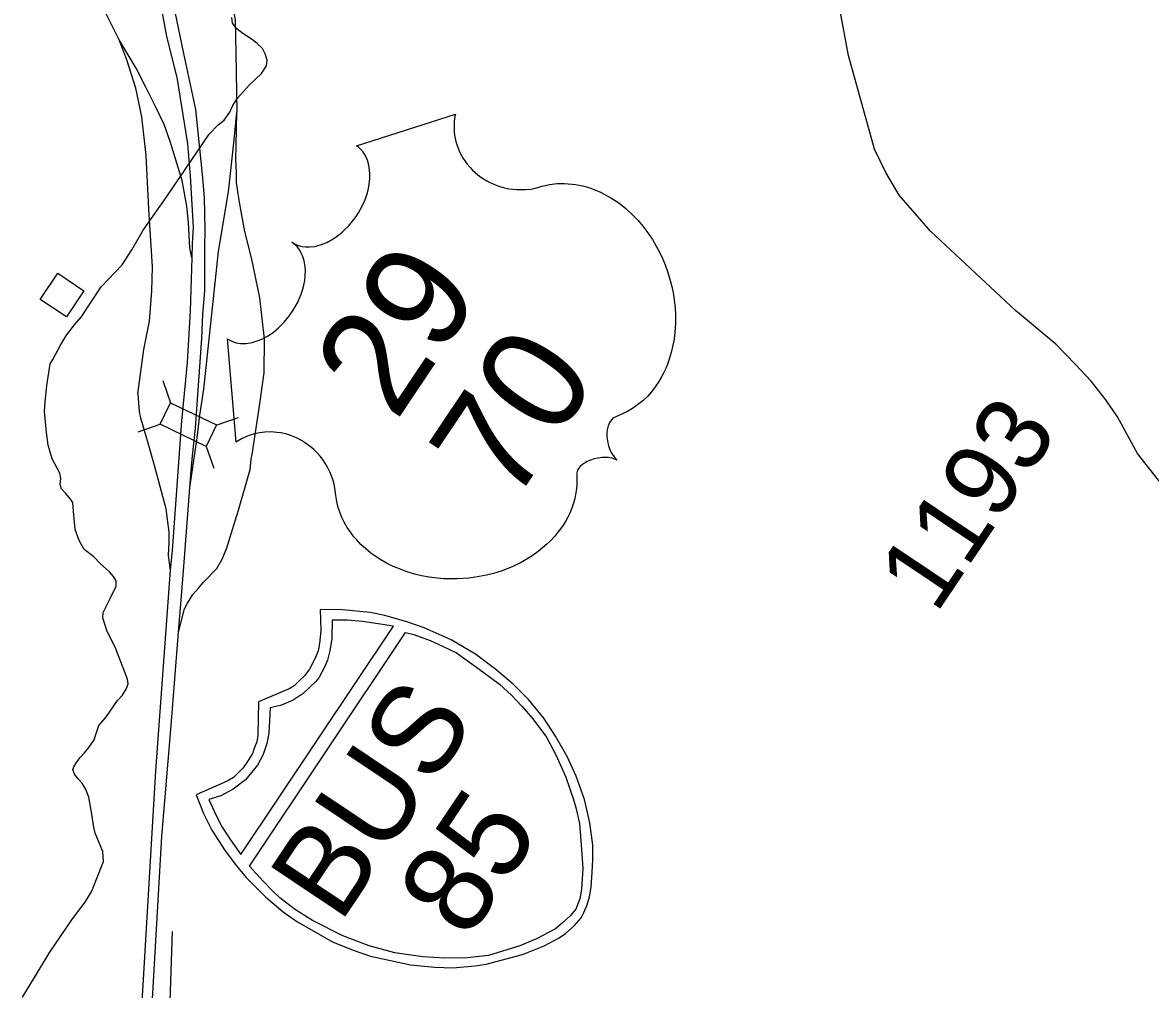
# Model space of a CAD drawing. Extents: x 1716282 to 1717158, y 799307 to 801078.
# Drawn here: x 1716546.8 to 1716655.2, y 800547.7 to 800640.6 of the extents above; entities that cross this region are included whole.
import ezdxf

# ---------------------------------------------------------------- set-up
doc = ezdxf.new("R2010")
doc.units = 0
for name, color, linetype in [('Exist Hydrographic Creek Single Shore', 7, 'Continuous'), ('Exist Road Non-System Structure Non-Sys NCDOT Attributed CELL', 7, 'Continuous'), ('Exist Road Non-System Structure Non-Sys Other Attributed CELL', 7, 'Continuous'), ('Exist Road Primary Interstate Divided Center Attributed', 7, 'Continuous'), ('Exist Road Primary Interstate Ramp 1 Lane Attributed', 7, 'Continuous'), ('Exist Road Secondary Type 51 Attributed', 7, 'Continuous'), ('Old_Level_1', 7, 'Continuous'), ('Old_Level_2', 7, 'Continuous')]:
    doc.layers.add(name, color=color, linetype=linetype)

msp = doc.modelspace()

# ---------------------------------------------------------------- linework, layer by layer
at = {"layer": 'Exist Hydrographic Creek Single Shore'}
for points in [[(1716551.4, 800594.83), (1716550.95, 800595.35), (1716550.56, 800595.81), (1716550.42, 800596.23), (1716550.49, 800596.81), (1716550.38, 800597.32), (1716549.64, 800598.68), (1716549.25, 800600.02), (1716549.1, 800601.22), (1716548.91, 800603.23), (1716548.96, 800604.17), (1716549.13, 800605.71), (1716549.27, 800606.57), (1716549.45, 800607.82), (1716549.71, 800608.25), (1716550.46, 800609.61), (1716551.04, 800610.58), (1716551.78, 800611.58), (1716552.43, 800612.32), (1716554.35, 800615.22), (1716556.37, 800617.34), (1716557.31, 800618.79), (1716558.39, 800620.68), (1716559.54, 800622.3), (1716560.68, 800623.92), (1716564.75, 800629.91), (1716565.6, 800630.8), (1716566.18, 800631.25), (1716566.73, 800632.01), (1716567.02, 800632.67), (1716567.46, 800633.36), (1716568.58, 800634.63), (1716569.76, 800635.74), (1716570.25, 800636.46), (1716570.31, 800637.02), (1716570.12, 800637.63), (1716569.88, 800638.14), (1716569.37, 800638.62), (1716568.92, 800638.97), (1716567.99, 800639.59), (1716567.4, 800640.02), (1716566.97, 800640.58), (1716566.92, 800641.11)], [(1716546.8, 800546.93), (1716547.95, 800548.84), (1716549.37, 800551.16), (1716551.53, 800554.38), (1716552.08, 800555.1), (1716552.83, 800556.06), (1716553.46, 800557.12), (1716553.92, 800558.28), (1716554.58, 800559.97), (1716554.53, 800560.93), (1716553.78, 800562.72), (1716553.61, 800563.44), (1716553.51, 800564.33), (1716553.17, 800566.16), (1716552.89, 800566.89), (1716552.54, 800567.5), (1716552.12, 800567.97), (1716551.78, 800568.37), (1716551.62, 800568.84), (1716551.77, 800569.14), (1716552.06, 800569.61), (1716552.34, 800569.97), (1716552.77, 800570.42), (1716553.18, 800570.95), (1716553.7, 800571.67), (1716553.87, 800572.28), (1716554.15, 800573.07), (1716554.74, 800573.75), (1716555.11, 800574.24), (1716555.92, 800575.45), (1716556.42, 800575.97), (1716556.77, 800576.56), (1716556.97, 800577.06), (1716556.89, 800577.51), (1716555.77, 800580.42), (1716554.91, 800582.18), (1716554.51, 800583.42), (1716554.56, 800583.92), (1716554.86, 800584.56), (1716555.24, 800585.26), (1716555.79, 800586.45), (1716555.8, 800586.96), (1716555.56, 800587.37), (1716555.15, 800587.82), (1716554.28, 800588.6), (1716553.67, 800589.27), (1716552.74, 800589.96), (1716552.23, 800590.85), (1716551.87, 800591.91), (1716551.7, 800593.65), (1716551.65, 800594.48), (1716551.4, 800594.83)]]:
    msp.add_lwpolyline(points, dxfattribs=at)
at = {"layer": 'Exist Road Non-System Structure Non-Sys NCDOT Attributed CELL'}
for p, q in [((1716560.3, 800606.21), (1716561.03, 800604.09)), ((1716557.91, 800601.3), (1716560.03, 800602.03)), ((1716565.43, 800601.94), (1716567.55, 800602.67)), ((1716564.44, 800599.89), (1716565.19, 800597.81))]:
    msp.add_line(p, q, dxfattribs=at)
msp.add_lwpolyline([(1716561.03, 800604.09), (1716565.44, 800601.95), (1716564.44, 800599.89), (1716560.03, 800602.03)], close=True, dxfattribs=at)
at = {"layer": 'Exist Road Non-System Structure Non-Sys Other Attributed CELL'}
msp.add_lwpolyline([(1716548.51, 800614.02), (1716550.19, 800616.53), (1716552.7, 800614.85), (1716551.02, 800612.34)], close=True, dxfattribs=at)
at = {"layer": 'Exist Road Primary Interstate Divided Center Attributed'}
for points in [[(1716558.5, 800649.75), (1716559.41, 800645.93), (1716560.64, 800639.31), (1716561.62, 800635.36), (1716562.66, 800628.98), (1716562.93, 800625.9), (1716563.2, 800620.92), (1716563.12, 800619.44), (1716563.06, 800618.01)], [(1716563.42, 800601.65), (1716564.03, 800610.28), (1716564.13, 800612.56), (1716564.31, 800614.83), (1716564.34, 800616.94), (1716564.33, 800619.08), (1716564.37, 800620.73), (1716564.28, 800623.82), (1716564.1, 800626.04), (1716563.45, 800632.27), (1716562.3, 800637.66), (1716560.63, 800645.71), (1716559.74, 800649.78)], [(1716563.06, 800618.01), (1716562.9, 800612.89), (1716562.62, 800607.99), (1716562.48, 800606.3), (1716562.07, 800602.34)], [(1716562.07, 800602.34), (1716561.17, 800589.87), (1716560.99, 800587.98)], [(1716562.88, 800595.9), (1716563.01, 800597.56), (1716563.13, 800598.98), (1716563.42, 800601.65)], [(1716561.78, 800582.04), (1716562.05, 800585.14), (1716562.26, 800587.93), (1716562.88, 800595.9)], [(1716560.99, 800587.98), (1716559.59, 800568.69), (1716558.25, 800545.95), (1716557.97, 800539.29), (1716557.81, 800532.9)], [(1716558.45, 800531), (1716558.55, 800536.61), (1716559.23, 800545.66), (1716560.2, 800562.39), (1716561.08, 800573.07), (1716561.78, 800582.04)]]:
    msp.add_lwpolyline(points, dxfattribs=at)
at = {"layer": 'Exist Road Primary Interstate Ramp 1 Lane Attributed'}
for points in [[(1716556.09, 800638.97), (1716554.22, 800642.7), (1716553.9, 800643.44), (1716553.38, 800644.7), (1716552.96, 800646.13), (1716552.59, 800647.62), (1716552.15, 800649.72)], [(1716565.79, 800649.91), (1716567.23, 800640.82), (1716567.3, 800637.71), (1716567.39, 800632.02)], [(1716557.88, 800604.95), (1716558.45, 800609.2), (1716559.01, 800611.93), (1716559.24, 800614.84), (1716559.31, 800617.16), (1716558.95, 800622.69), (1716558.69, 800627.87), (1716558.27, 800631.56), (1716557.69, 800634.34), (1716556.84, 800637.05), (1716556.09, 800638.97)], [(1716563.06, 800618.01), (1716562.88, 800618.98), (1716562.75, 800621.41), (1716562.61, 800622.99), (1716562.14, 800625.45), (1716561, 800629.21), (1716560.41, 800630.83), (1716559.6, 800632.5), (1716558.64, 800634.41), (1716557.73, 800636.24), (1716556.09, 800638.97)], [(1716562.88, 800595.9), (1716563.6, 800600.7), (1716563.86, 800602.89), (1716564.22, 800605.38), (1716565.63, 800618.62), (1716566.59, 800624.36), (1716567.13, 800629.35), (1716567.39, 800632.02)], [(1716568.87, 800599.11), (1716569.51, 800603.34), (1716570.03, 800606.97), (1716570.06, 800610.21), (1716569.61, 800614.18), (1716568.83, 800617.89), (1716568.16, 800620.56), (1716567.76, 800622.82), (1716567.53, 800624.18), (1716567.38, 800625.25), (1716567.38, 800626.26), (1716567.29, 800627.5), (1716567.34, 800628.78), (1716567.39, 800632.02)], [(1716557.88, 800604.95), (1716557.97, 800603.62), (1716558.05, 800603.01), (1716558.15, 800602.63), (1716558.26, 800602.23), (1716558.86, 800600.22), (1716559.47, 800598.09), (1716560.03, 800595.94), (1716560.56, 800593.92), (1716560.7, 800592.85), (1716560.85, 800591.63), (1716560.87, 800590.7), (1716560.81, 800589.4), (1716560.99, 800587.98)], [(1716561.78, 800582.04), (1716562.38, 800584.26), (1716562.65, 800584.83), (1716563.16, 800585.66), (1716563.72, 800586.27), (1716564.21, 800586.85), (1716565.47, 800588.16), (1716565.95, 800588.97), (1716566.41, 800590.05), (1716566.71, 800590.98), (1716567.55, 800593.76), (1716568.67, 800597.68), (1716568.79, 800598.67), (1716568.87, 800599.11)]]:
    msp.add_lwpolyline(points, dxfattribs=at)
at = {"layer": 'Exist Road Secondary Type 51 Attributed'}
for points in [[(1716695.67, 800558.39), (1716688.08, 800565.49), (1716681.92, 800571.19), (1716675.73, 800576.67), (1716668.88, 800582.96), (1716664.29, 800587.01), (1716662.56, 800588.64), (1716660.27, 800591.22), (1716653.98, 800599.21), (1716652.07, 800602.74), (1716650.94, 800604.38), (1716649.53, 800606.17), (1716648.03, 800607.76), (1716646.14, 800609.72), (1716642.26, 800612.96), (1716634.1, 800620.58), (1716631.07, 800624.03), (1716629.78, 800626.22), (1716628.69, 800628.46), (1716626.21, 800637.47), (1716625.41, 800641.76), (1716625.31, 800647.59), (1716627.05, 800656.51), (1716628.42, 800665.05)], [(1716560.43, 800531.91), (1716560.4, 800533.68), (1716560.71, 800540.38), (1716560.99, 800546.56), (1716561.23, 800553.26)]]:
    msp.add_lwpolyline(points, dxfattribs=at)
at = {"layer": 'Old_Level_2'}
for points in [[(1716566.5, 800610.22), (1716566.78, 800610.06), (1716567.14, 800609.91), (1716567.34, 800609.85), (1716567.76, 800609.79), (1716568.29, 800609.79), (1716568.88, 800609.88), (1716569.46, 800610.06), (1716569.8, 800610.21), (1716570.34, 800610.49), (1716570.88, 800610.85), (1716571.42, 800611.3), (1716571.92, 800611.79), (1716572.4, 800612.37), (1716572.83, 800612.98), (1716573.22, 800613.68), (1716573.57, 800614.51), (1716573.71, 800614.91), (1716573.84, 800615.38), (1716573.93, 800615.83), (1716573.98, 800616.35), (1716573.99, 800616.8), (1716573.97, 800617.16), (1716573.88, 800617.72), (1716573.72, 800618.22), (1716573.6, 800618.47), (1716573.49, 800618.69), (1716573.19, 800619.09), (1716573.04, 800619.24), (1716572.7, 800619.51), (1716573.01, 800619.33), (1716573.22, 800619.23), (1716573.44, 800619.16), (1716573.69, 800619.11), (1716574.05, 800619.06), (1716574.39, 800619.06), (1716574.92, 800619.12), (1716575.21, 800619.19), (1716575.46, 800619.26), (1716576.05, 800619.5), (1716576.66, 800619.84), (1716576.94, 800620.02), (1716577.2, 800620.22), (1716577.52, 800620.48), (1716577.83, 800620.77), (1716578.12, 800621.07), (1716578.4, 800621.38), (1716578.66, 800621.71), (1716578.86, 800621.99), (1716579.09, 800622.35), (1716579.29, 800622.69), (1716579.47, 800623.04), (1716579.66, 800623.45), (1716579.79, 800623.79), (1716579.95, 800624.25), (1716580.06, 800624.69), (1716580.13, 800625.09), (1716580.19, 800625.63), (1716580.2, 800626.09), (1716580.17, 800626.46), (1716580.1, 800626.92), (1716579.97, 800627.39), (1716579.85, 800627.7), (1716579.69, 800627.97), (1716579.51, 800628.24), (1716579.3, 800628.47), (1716579.09, 800628.65), (1716578.9, 800628.79), (1716588.41, 800631.82), (1716588.36, 800631.62), (1716588.3, 800631.16), (1716588.28, 800630.77), (1716588.29, 800630.11), (1716588.34, 800629.8), (1716588.39, 800629.49), (1716588.46, 800629.19), (1716588.54, 800628.91), (1716588.67, 800628.55), (1716588.82, 800628.21), (1716589, 800627.85), (1716589.17, 800627.56), (1716589.55, 800627.02), (1716589.82, 800626.7), (1716590.06, 800626.45), (1716590.58, 800625.99), (1716590.85, 800625.78), (1716591.12, 800625.6), (1716591.42, 800625.42), (1716591.71, 800625.27), (1716592.03, 800625.12), (1716592.32, 800625), (1716592.68, 800624.87), (1716593.12, 800624.75), (1716593.56, 800624.66), (1716594.32, 800624.57), (1716595.15, 800624.57), (1716595.65, 800624.63), (1716596.11, 800624.71), (1716596.72, 800624.89), (1716597.05, 800624.97), (1716597.47, 800625.06), (1716598.21, 800625.15), (1716598.54, 800625.16), (1716598.9, 800625.16), (1716599.26, 800625.14), (1716599.64, 800625.11), (1716599.96, 800625.07), (1716600.67, 800624.93), (1716601.32, 800624.73), (1716601.66, 800624.62), (1716602.37, 800624.32), (1716602.72, 800624.15), (1716603.37, 800623.79), (1716604.13, 800623.29), (1716604.8, 800622.75), (1716605.54, 800622.06), (1716605.97, 800621.62), (1716606.43, 800621.06), (1716606.82, 800620.56), (1716607.36, 800619.77), (1716607.72, 800619.15), (1716608.12, 800618.38), (1716608.35, 800617.9), (1716608.57, 800617.35), (1716608.81, 800616.7), (1716609.04, 800615.97), (1716609.25, 800615.14), (1716609.37, 800614.49), (1716609.49, 800613.68), (1716609.54, 800613.21), (1716609.57, 800612.55), (1716609.57, 800611.69), (1716609.52, 800610.87), (1716609.44, 800610.2), (1716609.33, 800609.62), (1716609.17, 800608.9), (1716608.79, 800607.77), (1716608.63, 800607.37), (1716608.41, 800606.92), (1716608.19, 800606.51), (1716607.97, 800606.12), (1716607.63, 800605.61), (1716607.25, 800605.13), (1716606.87, 800604.7), (1716606.43, 800604.28), (1716605.93, 800603.87), (1716605.44, 800603.52), (1716604.88, 800603.2), (1716603.84, 800602.74), (1716603.56, 800602.59), (1716603.44, 800602.48), (1716603.22, 800602.18), (1716603.09, 800601.85), (1716603, 800601.47), (1716602.98, 800601.23), (1716602.98, 800600.88), (1716603, 800600.6), (1716603.06, 800600.24), (1716603.14, 800599.97), (1716603.19, 800599.76), (1716603.4, 800599.29), (1716603.51, 800599.1), (1716603.68, 800598.87), (1716603.95, 800598.58), (1716603.47, 800598.75), (1716603.13, 800598.81), (1716602.8, 800598.83), (1716602.51, 800598.82), (1716602.09, 800598.77), (1716601.76, 800598.7), (1716601.4, 800598.58), (1716601.07, 800598.43), (1716600.82, 800598.29), (1716600.62, 800598.15), (1716600.41, 800597.95), (1716600.26, 800597.77), (1716600.16, 800597.61), (1716600.07, 800597.36), (1716600.08, 800596.93), (1716600.09, 800596.52), (1716600.07, 800596.1), (1716600.02, 800595.61), (1716599.97, 800595.26), (1716599.88, 800594.87), (1716599.76, 800594.42), (1716599.59, 800593.95), (1716599.4, 800593.48), (1716599.22, 800593.09), (1716598.99, 800592.68), (1716598.77, 800592.32), (1716598.52, 800591.96), (1716598.27, 800591.64), (1716597.97, 800591.27), (1716597.57, 800590.82), (1716597.21, 800590.48), (1716596.8, 800590.13), (1716596.37, 800589.78), (1716595.88, 800589.43), (1716595.23, 800589.01), (1716594.74, 800588.74), (1716593.94, 800588.34), (1716592.9, 800587.94), (1716592.06, 800587.68), (1716591.4, 800587.51), (1716590.36, 800587.31), (1716589.7, 800587.23), (1716588.59, 800587.15), (1716587.81, 800587.14), (1716587.26, 800587.17), (1716586.4, 800587.24), (1716585.88, 800587.32), (1716585.14, 800587.46), (1716584.49, 800587.62), (1716583.88, 800587.79), (1716583.51, 800587.92), (1716582.87, 800588.17), (1716582.43, 800588.35), (1716581.84, 800588.64), (1716581.24, 800588.99), (1716580.71, 800589.33), (1716580.28, 800589.63), (1716579.81, 800590.03), (1716579.32, 800590.47), (1716578.93, 800590.89), (1716578.66, 800591.2), (1716578.35, 800591.61), (1716578.02, 800592.1), (1716577.73, 800592.6), (1716577.51, 800593.04), (1716577.3, 800593.55), (1716577.15, 800594.02), (1716577.01, 800594.6), (1716576.91, 800595.16), (1716576.86, 800595.65), (1716576.75, 800596.27), (1716576.66, 800596.61), (1716576.5, 800597.06), (1716576.34, 800597.44), (1716576.18, 800597.76), (1716575.94, 800598.21), (1716575.73, 800598.52), (1716575.4, 800598.96), (1716575.14, 800599.24), (1716574.8, 800599.58), (1716574.46, 800599.88), (1716574.01, 800600.21), (1716573.62, 800600.45), (1716573.14, 800600.7), (1716572.65, 800600.91), (1716572.21, 800601.06), (1716571.67, 800601.18), (1716571.26, 800601.24), (1716570.67, 800601.28), (1716570.09, 800601.27), (1716569.57, 800601.2), (1716569.09, 800601.1), (1716568.69, 800600.97), (1716568.33, 800600.84), (1716567.91, 800600.64), (1716567.54, 800600.43), (1716567.33, 800600.28)], [(1716600.49, 800554.55), (1716600.76, 800555.07), (1716601.07, 800555.8), (1716601.29, 800556.57), (1716601.45, 800557.5), (1716601.57, 800558.95), (1716601.64, 800560.13), (1716601.64, 800561.56), (1716601.32, 800563.69), (1716600.82, 800565.95), (1716600.02, 800568.18), (1716599.17, 800570.09), (1716598.03, 800572.04), (1716596.91, 800573.77), (1716595.48, 800575.52), (1716593.98, 800577.04), (1716592.29, 800578.43), (1716590.36, 800579.9), (1716588, 800581.28), (1716585.42, 800582.44), (1716583.73, 800583.03), (1716581.63, 800583.63), (1716580.22, 800583.91), (1716577.56, 800584.16), (1716575.42, 800584.21), (1716575.47, 800582.17), (1716575.34, 800580.95), (1716575.22, 800580.23), (1716574.95, 800579.59), (1716574.38, 800578.46), (1716573.91, 800577.83), (1716573.37, 800577.31), (1716572.91, 800576.87), (1716572.43, 800576.59), (1716569.47, 800575.32), (1716569.41, 800572.09), (1716569.31, 800571.48), (1716569.09, 800570.93), (1716568.91, 800570.37), (1716568.43, 800569.58), (1716568.02, 800569), (1716567.51, 800568.47), (1716567.09, 800568.06), (1716566.47, 800567.7), (1716563.48, 800566.38), (1716564.19, 800564.6), (1716564.99, 800563), (1716566.29, 800561), (1716567.38, 800559.57), (1716568.31, 800558.45), (1716570.16, 800556.59), (1716571.87, 800555.13), (1716573.16, 800554.21), (1716576.6, 800552.26), (1716578.59, 800551.45), (1716580.25, 800550.87), (1716584.11, 800550.04), (1716586.43, 800549.81), (1716588.18, 800549.77), (1716590.3, 800549.94), (1716591.36, 800550.1), (1716594.87, 800551.04), (1716596.93, 800551.87), (1716598.4, 800552.64), (1716599, 800553.07), (1716599.84, 800553.79)], [(1716564.72, 800565.95), (1716565.21, 800564.81), (1716565.94, 800563.39), (1716566.8, 800562.07), (1716567.77, 800560.65), (1716582.46, 800582.59), (1716580.98, 800582.84), (1716579.47, 800583.06), (1716578.04, 800583.19), (1716576.57, 800583.17), (1716576.52, 800581.42), (1716576.34, 800580.24), (1716576.11, 800579.35), (1716575.84, 800578.65), (1716575.28, 800577.65), (1716574.97, 800577.25), (1716573.79, 800576.13), (1716572.83, 800575.48), (1716571.69, 800575.01), (1716570.59, 800574.76), (1716570.47, 800572.32), (1716570.3, 800571.32), (1716569.93, 800570.28), (1716569.4, 800569.23), (1716568.24, 800567.84), (1716567.05, 800566.94), (1716565.85, 800566.28)], [(1716583.63, 800581.99), (1716584.41, 800581.81), (1716586, 800581.22), (1716587.18, 800580.68), (1716588.51, 800580.03), (1716590.56, 800578.57), (1716592.66, 800577.02), (1716593.81, 800575.97), (1716594.8, 800574.92), (1716595.85, 800573.69), (1716597.17, 800571.95), (1716598.09, 800570.17), (1716599.03, 800568.08), (1716599.72, 800566.04), (1716599.99, 800565.17), (1716600.33, 800563.63), (1716600.55, 800561.12), (1716600.65, 800559.32), (1716600.53, 800557.32), (1716600.37, 800556.38), (1716599.98, 800555.41), (1716599.46, 800554.75), (1716598.67, 800554.05), (1716598.03, 800553.5), (1716596.22, 800552.54), (1716594.6, 800551.87), (1716591.59, 800550.96), (1716589.58, 800550.72), (1716587.4, 800550.7), (1716585.27, 800550.82), (1716582.6, 800551.2), (1716580.11, 800551.87), (1716577.59, 800552.84), (1716574.69, 800554.3), (1716573.04, 800555.35), (1716571.53, 800556.5), (1716570.81, 800557.2), (1716569.93, 800558.08), (1716568.62, 800559.53)]]:
    msp.add_lwpolyline(points, close=True, dxfattribs=at)

# ---------------------------------------------------------------- texts
at = {"layer": 'Old_Level_1'}
msp.add_text('1193', height=7.128, rotation=56.2051, dxfattribs=at).set_placement((1716634.62, 800583.69))
at = {"layer": 'Old_Level_2'}
for s, height, p in [('29', 10.093, (1716582.69, 800602.19)), ('70', 10.093, (1716593.87, 800594.1)), ('BUS', 8.564, (1716577.31, 800553.91)), ('85', 8.564, (1716589.57, 800552.29))]:
    msp.add_text(s, height=height, rotation=56.2051, dxfattribs=at).set_placement(p)

doc.saveas('drawing.dxf')
